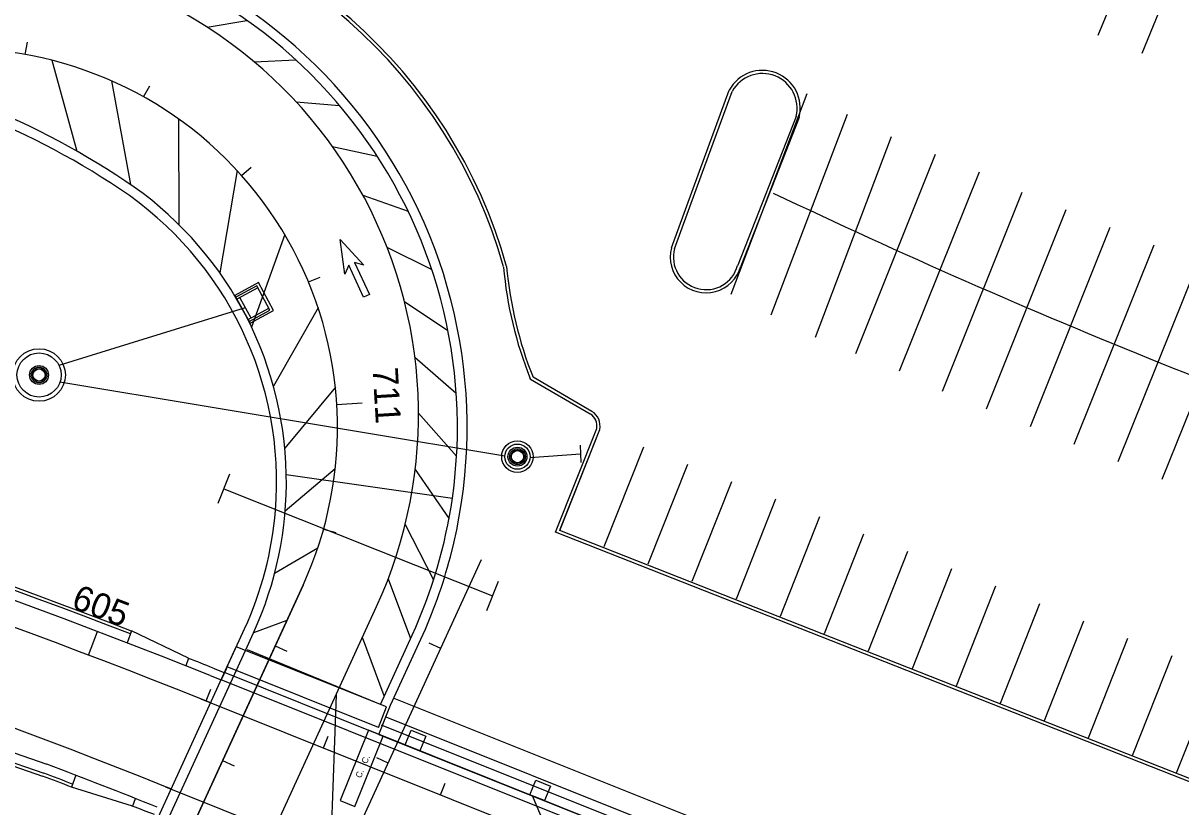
# Model space of a CAD drawing. Extents: x 468143 to 491361, y 1438528 to 1468730.
# Drawn here: x 487920.8 to 488104.2, y 1467199.5 to 1467323.7 of the extents above; entities that cross this region are included whole.
import ezdxf

# ---------------------------------------------------------------- set-up
doc = ezdxf.new("R2010")
doc.units = 0
doc.layers.add('Default', color=7, linetype='Continuous')
doc.layers.add('Xreference_dp', color=7, linetype='Continuous')

# ---------------------------------------------------------------- blocks, each defined once
blk = doc.blocks.new('POINT_DISPLAY')
at = {"layer": 'Default'}
blk.add_line((0, 0), (0, 0), dxfattribs=at)
blk = doc.blocks.new('PBottom40Dia_3')
at = {"layer": 'Default'}
for radius in [2.5, 2, 2]:
    blk.add_circle((0, 0), radius, dxfattribs=at)
for p in [(-0.75, 1.85), (0, 2), (0, 2), (0, 2), (-2, 0), (-2, 0), (-1.83, 0.81), (-1.39, 1.43), (0, 0), (0, 0), (0.81, 1.83), (1.43, 1.39), (1.85, 0.75), (2, 0), (2, 0), (-1.85, -0.75), (-1.43, -1.39), (-0.81, -1.83), (1.39, -1.43), (1.83, -0.81), (0, -2), (0, -2), (0, -2), (0.75, -1.85)]:
    blk.add_blockref('POINT_DISPLAY', p, dxfattribs=at)
blk = doc.blocks.new('JBottom70Dia_2')
at = {"layer": 'Default'}
for radius in [4.17, 3.5, 3.5]:
    blk.add_circle((0, 0), radius, dxfattribs=at)
for p in [(-2.44, 2.51), (-1.32, 3.24), (0, 3.5), (0, 3.5), (0, 3.5), (1.41, 3.2), (2.51, 2.44), (-3.5, 0), (-3.5, 0), (-3.2, 1.41), (0, 0), (0, 0), (0, 0), (3.24, 1.32), (3.5, 0), (3.5, 0), (-3.24, -1.32), (3.2, -1.41), (-2.51, -2.44), (-1.41, -3.2), (0, -3.5), (0, -3.5), (0, -3.5), (1.32, -3.24), (2.44, -2.51)]:
    blk.add_blockref('POINT_DISPLAY', p, dxfattribs=at)
blk = doc.blocks.new('DAMerge_2')
at = {"layer": 'Default'}
blk.add_lwpolyline([(0.71, -4.09), (0, -3.39), (3.95, 0.56), (2.42, 0.68), (7.31, 3.21), (4.77, -1.68), (4.66, -0.15), (0.71, -4.09)], dxfattribs=at)
blk = doc.blocks.new('DAMerge_6')
at = {"layer": 'Default'}
blk.add_lwpolyline([(0.71, -4.09), (0, -3.39), (3.95, 0.56), (2.42, 0.68), (7.31, 3.21), (4.77, -1.68), (4.66, -0.15), (0.71, -4.09)], dxfattribs=at)

msp = doc.modelspace()

# ---------------------------------------------------------------- linework, layer by layer
at = {"layer": 'Xreference_dp'}
for p, q in [((488091.16, 1467321.78), (488104.03, 1467353.25)), ((488098.1, 1467318.94), (488110.97, 1467350.41)), ((487949.98, 1467323.05), (487956.27, 1467324.13)), ((487921.18, 1467318.71), (487921.53, 1467320.68)), ((487925.37, 1467317.81), (487929.34, 1467303.41)), ((487957.42, 1467317.57), (487964.05, 1467317.86)), ((487934.85, 1467314.55), (487937.83, 1467298.13)), ((487939.93, 1467312.01), (487940.91, 1467313.76)), ((488032.98, 1467280.75), (488045.06, 1467312.53)), ((487964.08, 1467311.23), (487970.97, 1467310.65)), ((487945.43, 1467308.53), (487945.52, 1467291.76)), ((488039.36, 1467277.47), (488051.44, 1467309.24)), ((487969.85, 1467304.13), (487976.93, 1467302.62)), ((488046.34, 1467273.95), (488058.42, 1467305.72)), ((488052.73, 1467271.37), (488065.38, 1467302.93)), ((487954.74, 1467300.33), (487951.98, 1467284.14)), ((487955.45, 1467299.55), (487956.95, 1467300.88)), ((488059.69, 1467268.58), (488072.34, 1467300.14)), ((488066.47, 1467265.37), (488079.13, 1467296.93)), ((487974.68, 1467296.41), (487981.82, 1467293.91)), ((488073.44, 1467262.58), (488086.09, 1467294.14)), ((488080.4, 1467259.79), (488093.05, 1467291.35)), ((487962.28, 1467290.21), (487957.03, 1467275.52)), ((487978.48, 1467288.2), (487985.58, 1467284.65)), ((488087.36, 1467257), (488100.01, 1467288.55)), ((488094.32, 1467254.21), (488106.97, 1467285.76)), ((487958.14, 1467282.57), (487954.4, 1467280.54)), ((487957.86, 1467282.04), (487954.56, 1467280.25)), ((487959.92, 1467278.23), (487957.86, 1467282.04)), ((487960.52, 1467278.17), (487958.14, 1467282.57)), ((487966.04, 1467282.69), (487967.89, 1467283.46)), ((488101.28, 1467251.41), (488113.94, 1467282.97)), ((487954.4, 1467280.54), (487956.79, 1467276.15)), ((487958.02, 1467281.74), (487954.72, 1467279.95)), ((487955.16, 1467280.19), (487956.91, 1467276.97)), ((487956.03, 1467278.58), (487926.52, 1467269.43)), ((487956.47, 1467276.73), (487959.77, 1467278.52)), ((487967.58, 1467278.58), (487960.5, 1467266.16)), ((487981.23, 1467279.61), (487988.14, 1467274.99)), ((487956.63, 1467276.44), (487959.92, 1467278.23)), ((487956.79, 1467276.15), (487960.52, 1467278.17)), ((487923.68, 1467268.94), (487923.74, 1467269.13)), ((487982.9, 1467270.79), (487989.46, 1467265.08)), ((487922.36, 1467268.26), (487922.17, 1467268.32)), ((487922.37, 1467268.3), (487922.19, 1467268.37)), ((487922.23, 1467267.41), (487922.4, 1467267.5)), ((487922.25, 1467267.37), (487922.43, 1467267.45)), ((487922.87, 1467268.87), (487922.79, 1467269.05)), ((487922.92, 1467268.9), (487922.83, 1467269.07)), ((487923.73, 1467268.93), (487923.79, 1467269.11)), ((487924.29, 1467268.43), (487924.47, 1467268.51)), ((487924.32, 1467268.38), (487924.49, 1467268.47)), ((487924.53, 1467267.51), (487924.35, 1467267.57)), ((487924.55, 1467267.56), (487924.36, 1467267.62)), ((487922.93, 1467266.77), (487923, 1467266.95)), ((487922.98, 1467266.75), (487923.04, 1467266.94)), ((487923.89, 1467266.81), (487923.8, 1467266.98)), ((487923.93, 1467266.83), (487923.85, 1467267.01)), ((487997.16, 1467255.1), (487926.67, 1467266.81)), ((487970.31, 1467266), (487962.29, 1467256.33)), ((487970.53, 1467263.29), (487974.53, 1467263.54)), ((487983.47, 1467261.87), (487989.51, 1467255.09)), ((488005.93, 1467243.52), (488012.18, 1467259.33)), ((488009.07, 1467256.81), (488009.2, 1467254.09)), ((488012.9, 1467240.76), (488019.15, 1467256.57)), ((487998.1, 1467255.03), (487997.9, 1467255.04)), ((487998.1, 1467255.08), (487997.91, 1467255.09)), ((487998.43, 1467255.76), (487998.3, 1467255.91)), ((487998.47, 1467255.8), (487998.34, 1467255.94)), ((487999.18, 1467256.05), (487999.19, 1467256.25)), ((487999.23, 1467256.05), (487999.24, 1467256.25)), ((487999.92, 1467255.72), (488000.06, 1467255.85)), ((487999.95, 1467255.68), (488000.1, 1467255.82)), ((488000.4, 1467254.96), (488000.2, 1467254.97)), ((488000.4, 1467254.91), (488000.2, 1467254.92)), ((488001.15, 1467254.89), (488009.13, 1467255.46)), ((487970.28, 1467253.08), (487962.35, 1467246.35)), ((487982.95, 1467252.98), (487988.31, 1467245.17)), ((487998.21, 1467254.18), (487998.35, 1467254.31)), ((487998.24, 1467254.14), (487998.39, 1467254.28)), ((487999.06, 1467253.75), (487999.07, 1467253.95)), ((487999.11, 1467253.75), (487999.12, 1467253.95)), ((487999.97, 1467254.05), (487999.84, 1467254.2)), ((488000.01, 1467254.09), (487999.88, 1467254.23)), ((488019.88, 1467238), (488026.13, 1467253.81)), ((487953.55, 1467252.21), (487951.69, 1467247.56)), ((487962.53, 1467252.19), (487988.84, 1467248.42)), ((488026.85, 1467235.25), (488033.1, 1467251.06)), ((487952.62, 1467249.88), (487995.21, 1467232.94)), ((488033.83, 1467232.49), (488040.08, 1467248.3)), ((488040.8, 1467229.73), (488047.05, 1467245.54)), ((487968.43, 1467243.5), (487970.36, 1467242.96)), ((487981.36, 1467244.24), (487985.86, 1467235.48)), ((488047.78, 1467226.98), (488054.02, 1467242.78)), ((487967.51, 1467240.5), (487960.68, 1467236.5)), ((488054.75, 1467224.22), (488061, 1467240.03)), ((487859.77, 1466947.15), (487993.45, 1467238.69)), ((487859.77, 1466947.15), (487993.45, 1467238.69)), ((488061.73, 1467221.46), (488067.97, 1467237.27)), ((487965.18, 1467234.63), (487923.5, 1467143.73)), ((487960.96, 1467225.43), (487965.18, 1467234.63)), ((487978.69, 1467235.67), (487982.21, 1467226.18)), ((487994.28, 1467230.62), (487996.14, 1467235.26)), ((488068.7, 1467218.71), (488074.95, 1467234.51)), ((487945.48, 1467162.86), (487976.83, 1467231.24)), ((488075.67, 1467215.95), (488081.92, 1467231.76)), ((487962.63, 1467229.06), (487957.33, 1467227.09)), ((488082.65, 1467213.19), (488088.9, 1467229)), ((487931.2, 1467223.57), (487932.62, 1467227.31)), ((487938.03, 1467227.38), (487937.31, 1467225.51)), ((487947.05, 1467223.05), (487938.03, 1467227.38)), ((487952.74, 1467220.78), (487955.93, 1467227.73)), ((487956.05, 1467224.3), (487957.33, 1467227.09)), ((487856.07, 1466996.67), (487960.96, 1467225.43)), ((487978.04, 1467217.09), (487974.6, 1467226.37)), ((487977.43, 1467215.75), (487982.46, 1467226.72)), ((487979.06, 1467215.61), (487983.86, 1467226.07)), ((487987, 1467224.63), (487985.18, 1467225.46)), ((488089.62, 1467210.43), (488095.87, 1467226.24)), ((487940.43, 1467193.93), (487954.61, 1467224.87)), ((487941.86, 1467193.36), (487956.05, 1467224.3)), ((487978.42, 1467215.35), (487954.61, 1467224.87)), ((487977.43, 1467215.75), (487956.37, 1467224.41)), ((487960.79, 1467225.04), (487962.6, 1467224.21)), ((488096.6, 1467207.68), (488102.85, 1467223.49)), ((487947.05, 1467223.05), (487946.6, 1467221.88)), ((487950.92, 1467221.51), (487952.68, 1467220.8)), ((487953.05, 1467221.46), (487952.21, 1467219.64)), ((487977.12, 1467212.1), (487953.15, 1467221.69)), ((487950.46, 1467220.35), (487952.21, 1467219.64)), ((488054.01, 1467178.92), (487952.21, 1467219.64)), ((487977.21, 1467210.99), (487952.74, 1467220.78)), ((488103.57, 1467204.92), (488109.82, 1467220.73)), ((487949.83, 1467216.29), (487950.57, 1467218.15)), ((487948.97, 1467216.63), (488191.23, 1467119.72)), ((487950.4, 1467216.06), (487948.97, 1467216.63)), ((487970.43, 1467217.28), (487969.51, 1467192.12)), ((487979.58, 1467216.75), (488053.51, 1467187.18)), ((487977.12, 1467212.1), (487978.42, 1467215.35)), ((487977.21, 1467210.99), (487979.06, 1467215.61)), ((487906, 1467212.65), (487924.61, 1467206.28)), ((487977.21, 1467210.99), (487978.32, 1467213.77)), ((488074.17, 1467173.86), (487977.62, 1467212.48)), ((487978.32, 1467213.77), (488074.59, 1467175.26)), ((487905.33, 1467210.77), (487923.93, 1467204.4)), ((487905.5, 1467211.24), (487924.1, 1467204.87)), ((487968.4, 1467208.86), (487969.14, 1467210.72)), ((488073.59, 1467172.43), (487975.55, 1467211.65)), ((487977.21, 1467210.99), (488073.48, 1467172.48)), ((487952.45, 1467206.86), (487954.27, 1467206.03)), ((487978.66, 1467206.45), (487976.85, 1467207.28)), ((487929.21, 1467204.52), (487928.49, 1467202.65)), ((487986.96, 1467201.43), (487987.71, 1467203.29)), ((487938.14, 1467199.63), (487928.49, 1467202.65)), ((487943.4, 1467202.7), (488185.65, 1467105.79)), ((487944.29, 1467202.35), (487943.4, 1467202.7)), ((487938.58, 1467200.8), (487938.14, 1467199.63)), ((488006.95, 1467188.61), (488001.53, 1467201.26))]:
    msp.add_line(p, q, dxfattribs=at)
for points in [[(488024.02, 1467287.95), (488028.48, 1467300.08), (488033.16, 1467312.88)], [(488028.01, 1467300.25), (488032.7, 1467313.09)], [(488043.29, 1467308.91), (488034.05, 1467285.33), (488034.04, 1467285.3)], [(488043.76, 1467308.75), (488034.53, 1467285.17)], [(488023.54, 1467288.1), (488028.01, 1467300.25)], [(487997.43, 1467285.14), (487997.43, 1467285.14)], [(488010.69, 1467261.75), (488001.23, 1467267.25), (488001.16, 1467267.41)], [(488010.95, 1467262.18), (488001.63, 1467267.6)], [(488179.25, 1467191.68), (488173.61, 1467176.7), (488005.2, 1467243.02), (488011.7, 1467259.47)], [(488178.8, 1467191.91), (488173.32, 1467177.35), (488005.84, 1467243.3), (488012.18, 1467259.33)]]:
    msp.add_lwpolyline(points, dxfattribs=at)
for points in [[(487977.87, 1467210.72), (487975.55, 1467211.65), (487971.09, 1467200.51), (487973.41, 1467199.58)], [(487982.29, 1467211.65), (487984.61, 1467210.72), (487983.69, 1467208.4), (487981.36, 1467209.33)], [(488002.04, 1467203.75), (488004.36, 1467202.82), (488003.43, 1467200.5), (488001.11, 1467201.43)]]:
    msp.add_lwpolyline(points, close=True, dxfattribs=at)
for centre, radius in [((487923.36, 1467267.94), 1.5), ((487923.36, 1467267.94), 1.25), ((487923.36, 1467267.94), 1.05), ((487923.36, 1467267.94), 1), ((487923.36, 1467267.94), 0.958), ((487999.15, 1467255), 1.5), ((487999.15, 1467255), 1.25), ((487999.15, 1467255), 1.05), ((487999.15, 1467255), 1), ((487999.15, 1467255), 0.958)]:
    msp.add_circle(centre, radius, dxfattribs=at)
for centre, radius, start, end in [((489087.46, 1469710.77), 2572.6, 246.52473, 249.53128), ((487919.22, 1467263.23), 80.73, 15.6822, 81.8262), ((487919.22, 1467263.23), 81.23, 15.6494, 81.8334), ((487910.64, 1467259.64), 80.54, 345.262, 83.9799), ((487910.64, 1467259.64), 79, 351.8301, 83.9799), ((487910.47, 1467261.67), 73, 335.3671, 84.1733), ((487910.64, 1467259.64), 60, 335.3671, 84.1733), ((487910.64, 1467259.64), 60, 335.3671, 84.1733), ((487867.08, 1467193.7), 124.61, 56.3538, 81.6244), ((487867.08, 1467193.7), 126.15, 56.3538, 81.6401), ((488037.96, 1467310.21), 5.99, 345.8816, 151.3412), ((488037.96, 1467310.21), 5.49, 346.2059, 150.9577), ((487905.21, 1467250.99), 57.33, 1.205, 56.3538), ((487905.21, 1467250.99), 55.79, 355.3286, 56.3538), ((488505.53, 1468275.2), 1083.68, 244.5388, 251.63312), ((487523.34, 1466152.69), 1151.92, 68.89997, 81.35759), ((487523.34, 1466152.69), 1149.92, 68.1961, 81.35759), ((487523.34, 1466152.69), 1151.42, 68.89997, 81.35759), ((488029.03, 1467286.64), 5.68, 165.0427, 345.0427), ((488029.03, 1467286.64), 5.18, 165.2898, 345.0427), ((487523.34, 1466152.69), 1145.92, 68.1961, 81.35759), ((487523.34, 1466152.69), 1145.92, 68.1961, 81.35759), ((488058.97, 1467290.58), 62.28, 185.098, 201.8401), ((488058.97, 1467290.58), 61.78, 185.0552, 201.8401), ((487523.34, 1466152.69), 1130.92, 68.1961, 81.35759), ((487523.34, 1466152.69), 1130.92, 68.1961, 81.35759), ((488009.56, 1467259.89), 2.68, 347.8241, 58.7257), ((488009.56, 1467259.89), 2.18, 348.8478, 58.6062), ((487905.21, 1467250.99), 57.33, 335.3671, 1.205), ((487910.64, 1467259.64), 79, 335.3671, 351.8301), ((487905.21, 1467250.99), 55.79, 335.3671, 355.3286), ((487910.64, 1467259.64), 80.54, 335.3671, 345.262), ((487910.64, 1467259.64), 80.54, 335.3671, 345.262), ((487910.64, 1467259.64), 80.54, 335.3671, 345.262), ((487523.34, 1466152.69), 1151.17, 68.1961, 68.40345), ((487523.34, 1466152.69), 1127.42, 68.1961, 69.14997), ((487523.34, 1466152.69), 1125.42, 68.89997, 69.14823), ((487523.34, 1466152.69), 1125.92, 68.89997, 69.14866), ((487416.74, 1465829.61), 1465.88, 69.01753, 69.16453)]:
    msp.add_arc(centre, radius, start, end, dxfattribs=at)

# ---------------------------------------------------------------- block references
for name, p, rotation in [('DAMerge_2', (487971.6, 1467281.42), 70.0207766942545), ('DAMerge_6', (487971.6, 1467281.42), 70.0207766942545), ('POINT_DISPLAY', (487955.16, 1467280.19), 118.49956014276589), ('POINT_DISPLAY', (487956.59, 1467280.97), 118.49956014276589), ('POINT_DISPLAY', (487956.59, 1467280.97), 118.49956014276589), ('POINT_DISPLAY', (487958.02, 1467281.74), 118.49956014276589), ('POINT_DISPLAY', (487958.89, 1467280.13), 118.49956014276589), ('POINT_DISPLAY', (487958.89, 1467280.13), 118.49956014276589), ('POINT_DISPLAY', (487959.33, 1467280.37), 118.49956014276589), ('POINT_DISPLAY', (487955.6, 1467278.34), 118.49956014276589), ('POINT_DISPLAY', (487955.6, 1467278.34), 118.49956014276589), ('POINT_DISPLAY', (487956.03, 1467278.58), 118.49956014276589), ('POINT_DISPLAY', (487956.03, 1467278.58), 118.49956014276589), ('POINT_DISPLAY', (487957.46, 1467279.36), 118.49956014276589), ('POINT_DISPLAY', (487957.46, 1467279.36), 118.49956014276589), ('POINT_DISPLAY', (487959.77, 1467278.52), 118.49956014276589), ('POINT_DISPLAY', (487956.91, 1467276.97), 118.49956014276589), ('POINT_DISPLAY', (487958.34, 1467277.75), 118.49956014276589), ('POINT_DISPLAY', (487958.34, 1467277.75), 118.49956014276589), ('JBottom70Dia_2', (487923.36, 1467267.94), 161.12416727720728), ('POINT_DISPLAY', (487923.85, 1467269.36), 161.12416727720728), ('POINT_DISPLAY', (487922.41, 1467268.26), 161.12416727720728), ('POINT_DISPLAY', (487922.46, 1467267.5), 161.12416727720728), ('POINT_DISPLAY', (487922.92, 1467268.84), 161.12416727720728), ('POINT_DISPLAY', (487923.36, 1467267.94), 161.12416727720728), ('POINT_DISPLAY', (487923.36, 1467267.94), 161.12416727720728), ('POINT_DISPLAY', (487923.36, 1467267.94), 161.12416727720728), ('POINT_DISPLAY', (487923.68, 1467268.89), 161.12416727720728), ('POINT_DISPLAY', (487924.26, 1467268.38), 161.12416727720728), ('POINT_DISPLAY', (487924.31, 1467267.62), 161.12416727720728), ('POINT_DISPLAY', (487922.88, 1467266.52), 161.12416727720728), ('POINT_DISPLAY', (487923.04, 1467266.99), 161.12416727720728), ('POINT_DISPLAY', (487923.8, 1467267.04), 161.12416727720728), ('PBottom40Dia_3', (487999.15, 1467255), 176.9962758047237), ('POINT_DISPLAY', (487999.23, 1467256.5), 176.9962758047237), ('POINT_DISPLAY', (487998.15, 1467255.05), 176.9962758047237), ('POINT_DISPLAY', (487998.48, 1467255.74), 176.9962758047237), ('POINT_DISPLAY', (487999.15, 1467255), 176.9962758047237), ('POINT_DISPLAY', (487999.15, 1467255), 176.9962758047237), ('POINT_DISPLAY', (487999.15, 1467255), 176.9962758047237), ('POINT_DISPLAY', (487999.21, 1467256), 176.9962758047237), ('POINT_DISPLAY', (487999.9, 1467255.67), 176.9962758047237), ('POINT_DISPLAY', (488000.15, 1467254.95), 176.9962758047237), ('POINT_DISPLAY', (487998.41, 1467254.33), 176.9962758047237), ('POINT_DISPLAY', (487999.07, 1467253.5), 176.9962758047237), ('POINT_DISPLAY', (487999.1, 1467254), 176.9962758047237), ('POINT_DISPLAY', (487999.82, 1467254.26), 176.9962758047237)]:
    msp.add_blockref(name, p, dxfattribs=dict(at, rotation=rotation))

# ---------------------------------------------------------------- texts
for s, height, rotation, p in [('711', 4, 273.4898, (487976.19, 1467269.04)), ('605', 4, 339.15, (487928.3, 1467231.09)), ('C.   C.', 1, 67.3606, (487974.35, 1467203.99))]:
    msp.add_text(s, height=height, rotation=rotation, dxfattribs=at).set_placement(p)

doc.saveas('drawing.dxf')
